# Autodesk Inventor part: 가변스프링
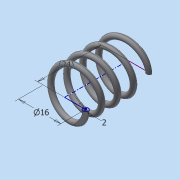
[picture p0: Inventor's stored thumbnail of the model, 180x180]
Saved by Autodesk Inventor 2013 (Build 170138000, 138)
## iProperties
Created: 2015-09
Part Number: 가변스프링
Material: 강철, 연강
Document SubType Name: Modeling
Designer: dgall
Density: 7.86 g/cm^3
Author: dgall
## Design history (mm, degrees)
sketch "스케치1"
  geometry: L1 (0, 0)-(8, 0); L2 (0, 0)-(0, 42); L3 (0, 42)-(8, 42); C1 r 1 at (8, 0)
  constraints: 6 end point, 2 perpendicular, 1 centre point, 1 coincident, 1 horizontal, 1 vertical alignment
  dimensions: "d0" = 2 diameter of C1; "d1" = 42 distance between parallel lines of L1 L3 (derived); "d2" = 16 diameter of L1.end L2
feature "코일1" pitch "d3" = 10; turns "d5" = 4; dims "d4" = 42 (= d1), "d6" = 0, angle "d7" = 90 deg, angle "d8" = 90 deg, "d9" = 0, "d10" = 0
node "작업 평면1"
feature "분할1"
feature "분할2"
node "솔리드1"
other parameters: "d11" = 24
